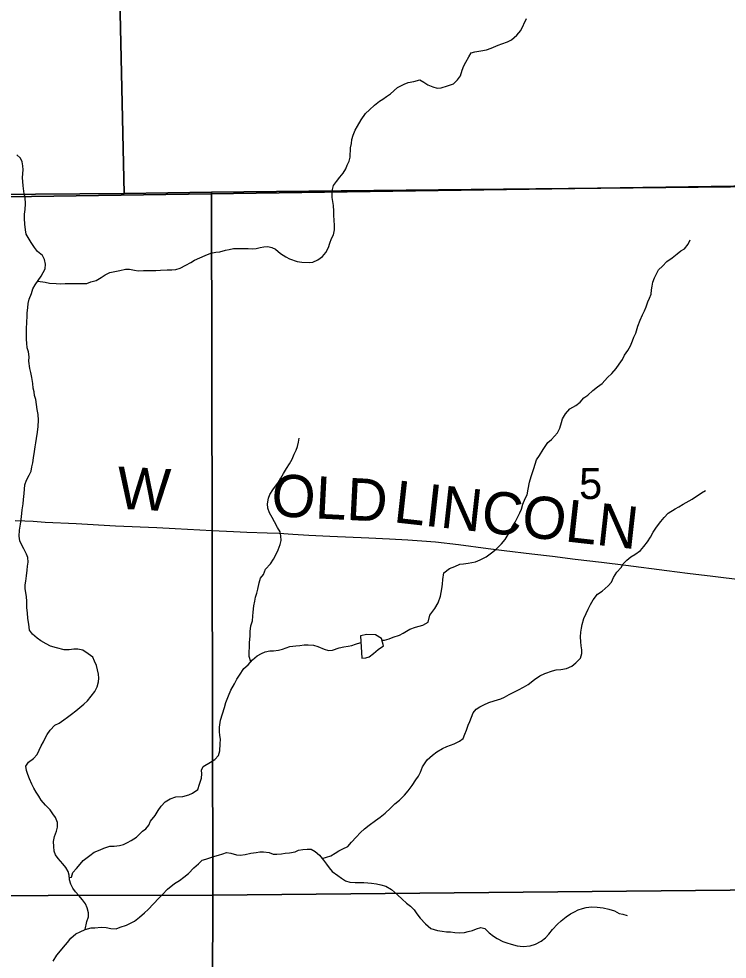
# Model space of a CAD drawing. Extents: x 1985906 to 2360102, y 891258 to 1222054.
# Drawn here: x 2080365 to 2085399, y 1019793 to 1026480 of the extents above; entities that cross this region are included whole.
import ezdxf

# ---------------------------------------------------------------- set-up
doc = ezdxf.new("R2010")
doc.units = 0
for name, color, linetype in [('GM_X_County_Road', 7, 'Continuous'), ('GM_X_County_Road_Text', 7, 'Continuous'), ('GM_X_Minor_Lake', 7, 'Continuous'), ('GM_X_Minor_River', 7, 'Continuous'), ('GM_X_Section', 7, 'Continuous'), ('GM_X_Section_Text', 7, 'Continuous'), ('GM_X_Township', 7, 'Continuous')]:
    doc.layers.add(name, color=color, linetype=linetype)

msp = doc.modelspace()

# ---------------------------------------------------------------- linework, layer by layer
at = {"layer": 'GM_X_County_Road'}
msp.add_lwpolyline([(2080338.1, 1022911.8), (2080407.5, 1022910), (2080466.6, 1022907.4), (2080551.7, 1022901.3), (2080773.4, 1022890.3), (2081051.5, 1022875.3), (2081346.3, 1022861.6), (2081477, 1022855.9), (2081738.7, 1022842.4), (2081889.7, 1022835.1), (2081985.2, 1022829.9), (2082129.4, 1022824.7), (2082215.4, 1022821.2), (2082311.9, 1022814.6), (2082426.6, 1022808.9), (2082574.1, 1022801.9), (2082852.1, 1022788.3), (2082999.5, 1022781.1), (2083130.5, 1022774.8), (2083228.7, 1022768.7), (2083326.6, 1022760.2), (2083489.5, 1022741.9), (2083701, 1022714.4), (2083815, 1022700.1), (2084010.3, 1022675.8), (2084156.8, 1022657.8), (2084319.6, 1022637.4), (2084505.1, 1022615.9), (2084678.7, 1022595), (2084970.8, 1022556.5), (2085117.1, 1022537.5), (2085296.1, 1022515.5), (2085507.3, 1022489.8)], dxfattribs=at)
at = {"layer": 'GM_X_Minor_Lake'}
for points in [[(2082802, 1021932.9), (2082830, 1021935.1), (2082855.9, 1021943.3), (2082885.8, 1021965.5), (2082919.6, 1021995.7), (2082957.5, 1022022), (2082943.2, 1022073.9), (2082899, 1022099.7), (2082839, 1022101.4), (2082793.1, 1022091.1)], [(2082793.1, 1022091.1), (2082802, 1021932.9)]]:
    msp.add_lwpolyline(points, dxfattribs=at)
at = {"layer": 'GM_X_Minor_River'}
for points in [[(2083307.3, 1025995.4), (2083337.4, 1025987.5), (2083365.4, 1025989.6), (2083411.4, 1026003.9), (2083453.4, 1026018.1), (2083483.4, 1026046.4), (2083503.2, 1026074.6), (2083515.1, 1026114.8), (2083526.9, 1026144.9), (2083540.8, 1026171.1), (2083562.7, 1026209.3), (2083580.5, 1026237.5), (2083606.5, 1026245.7), (2083648.6, 1026251.9), (2083688.6, 1026260.1), (2083722.6, 1026272.3), (2083770.6, 1026292.6), (2083798.6, 1026302.8), (2083838.6, 1026317), (2083866.6, 1026331.2), (2083904.5, 1026363.5), (2083932.4, 1026397.7), (2083974, 1026482.2)], [(2080499.5, 1024614.7), (2080553.2, 1024607.7), (2080583.3, 1024599.8), (2080629.4, 1024598), (2080661.4, 1024596.2), (2080693.5, 1024598.3), (2080791.7, 1024598.8), (2080817.7, 1024596.9), (2080847.8, 1024599), (2080875.8, 1024609.2), (2080913.8, 1024619.4), (2080949.8, 1024641.7), (2080977.7, 1024659.9), (2081011.7, 1024676.1), (2081047.7, 1024682.3), (2081083.8, 1024690.5), (2081123.8, 1024700.7), (2081151.8, 1024700.8), (2081187.9, 1024692.9), (2081214, 1024689), (2081252.1, 1024689.2), (2081278.1, 1024691.3), (2081312.2, 1024689.5), (2081338.3, 1024689.6), (2081372.3, 1024691.8), (2081418.4, 1024694), (2081452.4, 1024696.2), (2081480.5, 1024698.3), (2081512.5, 1024706.5), (2081552.5, 1024728.7), (2081588.4, 1024747), (2081614.4, 1024763.2), (2081650.4, 1024781.4), (2081688.4, 1024797.6), (2081728.4, 1024813.8), (2081764.4, 1024820), (2081794.4, 1024824.2), (2081834.5, 1024834.4), (2081860.5, 1024840.6), (2081890.5, 1024846.7), (2081994.7, 1024847.2), (2082026.8, 1024845.3), (2082052.8, 1024847.5), (2082080.8, 1024853.6), (2082106.9, 1024859.8), (2082134.9, 1024859.9), (2082163, 1024854), (2082189.1, 1024842.1), (2082225.3, 1024812.1), (2082261.5, 1024788.2), (2082287.7, 1024774.3), (2082343.9, 1024754.4), (2082376, 1024748.6), (2082428.1, 1024746.8), (2082454.1, 1024748.9), (2082490.1, 1024767.2), (2082522, 1024789.4), (2082547.9, 1024817.6), (2082565.8, 1024853.8), (2082575.6, 1024884), (2082587.5, 1024918.2), (2082601.4, 1024944.3), (2082609.2, 1024978.5), (2082609, 1025008.6), (2082606.8, 1025050.7), (2082604.7, 1025078.8), (2082604.5, 1025112.9), (2082600.3, 1025153.1), (2082592, 1025209.2), (2082591.8, 1025235.3), (2082593.7, 1025267.4), (2082601.5, 1025295.6), (2082623.4, 1025323.8), (2082645.3, 1025354), (2082669.2, 1025382.2), (2082689.1, 1025412.4), (2082699, 1025438.6), (2082712.9, 1025468.7), (2082718.7, 1025496.9), (2082722.4, 1025563.1), (2082728.2, 1025593.3), (2082732.1, 1025621.4), (2082742, 1025653.5), (2082755.8, 1025687.7), (2082771.7, 1025715.9), (2082797.5, 1025762.2), (2082829.3, 1025806.5), (2082857.2, 1025832.7), (2082893.2, 1025865), (2082927.1, 1025895.3), (2082953, 1025909.4), (2082979, 1025927.6), (2083007, 1025945.8), (2083056.8, 1025992.2), (2083102.8, 1026016.5), (2083132.8, 1026026.7), (2083172.8, 1026034.9), (2083214.8, 1026045.1), (2083243, 1026029.2), (2083271.1, 1026011.3), (2083307.3, 1025995.4)], [(2080383.5, 1022938.9), (2080389.3, 1022987.1), (2080395.1, 1023031.3), (2080398.9, 1023061.4), (2080402.7, 1023103.6), (2080404.5, 1023135.7), (2080408.4, 1023165.8), (2080420.2, 1023200), (2080438.1, 1023234.2), (2080451.9, 1023264.4), (2080457.8, 1023294.5), (2080463.7, 1023322.7), (2080469.5, 1023358.8), (2080475.3, 1023403), (2080481.1, 1023435.2), (2080485, 1023465.3), (2080490.8, 1023495.4), (2080496.6, 1023539.6), (2080502.4, 1023579.8), (2080504.2, 1023626), (2080502, 1023666.1), (2080495.8, 1023702.2), (2080485.4, 1023772.4), (2080477.2, 1023802.5), (2080473.1, 1023828.5), (2080466.9, 1023854.6), (2080464.7, 1023886.7), (2080456.5, 1023928.8), (2080450.3, 1023964.9), (2080444.1, 1023993), (2080435.9, 1024045.2), (2080437.7, 1024077.3), (2080433.5, 1024111.4), (2080425.4, 1024139.4), (2080421.2, 1024173.6), (2080419, 1024199.6), (2080418.6, 1024271.9), (2080422.4, 1024328.1), (2080424.2, 1024360.2), (2080424, 1024390.4), (2080427.9, 1024424.5), (2080431.7, 1024454.6), (2080439.6, 1024486.8), (2080455.4, 1024527), (2080465.2, 1024559.2), (2080481.1, 1024589.3), (2080503, 1024619.5), (2080524.9, 1024649.8), (2080552.7, 1024702.1), (2080554.5, 1024736.2), (2080546.3, 1024768.3), (2080534.2, 1024796.3), (2080497.9, 1024826.3), (2080475.7, 1024854.3), (2080453.5, 1024888.3), (2080437.4, 1024914.3), (2080417.1, 1024948.3), (2080413, 1024980.4), (2080408.7, 1025020.6), (2080406.5, 1025060.7), (2080406.4, 1025090.8), (2080410.2, 1025124.9), (2080412, 1025165.1), (2080409.8, 1025209.2), (2080403.6, 1025235.3), (2080395.3, 1025291.5), (2080391, 1025351.7), (2080394.7, 1025405.9), (2080392.6, 1025434), (2080388.4, 1025464.1), (2080376.2, 1025490.1), (2080350.1, 1025512.1)], [(2083425.3, 1022571.4), (2083463.3, 1022585.7), (2083499.3, 1022601.9), (2083525.3, 1022604), (2083559.4, 1022608.2), (2083609.4, 1022618.4), (2083643.4, 1022632.7), (2083685.4, 1022654.9), (2083725.3, 1022683.2), (2083757.2, 1022709.4), (2083795.1, 1022745.8), (2083821, 1022778), (2083850.8, 1022824.3), (2083868.7, 1022862.5), (2083892.5, 1022900.8), (2083926.2, 1022967.2), (2083938.1, 1022993.3), (2083947.9, 1023029.5), (2083963.8, 1023067.7), (2083977.7, 1023093.8), (2083985.5, 1023136), (2083995.2, 1023184.3), (2084007, 1023224.5), (2084024.8, 1023282.8), (2084044.5, 1023343.1), (2084064.4, 1023375.3), (2084090.2, 1023417.5), (2084124, 1023467.9), (2084149.9, 1023488.1), (2084193.8, 1023536.5), (2084209.6, 1023568.6), (2084221.5, 1023608.8), (2084229.3, 1023635), (2084249.2, 1023671.2), (2084281.1, 1023705.5), (2084323, 1023729.7), (2084355, 1023754), (2084380.9, 1023784.2), (2084408.8, 1023804.4), (2084444.7, 1023836.7), (2084478.6, 1023862.9), (2084510.6, 1023887.2), (2084548.4, 1023929.5), (2084578.3, 1023957.7), (2084610.2, 1023994), (2084632.1, 1024024.2), (2084654, 1024058.4), (2084669.8, 1024088.6), (2084693.7, 1024120.9), (2084711.6, 1024155.1), (2084725.4, 1024189.3), (2084735.3, 1024215.4), (2084749.2, 1024245.6), (2084762.9, 1024293.8), (2084780.8, 1024338), (2084796.6, 1024374.2), (2084810.5, 1024404.4), (2084824.3, 1024432.6), (2084834.2, 1024466.8), (2084848.1, 1024492.9), (2084858, 1024521.1), (2084861.8, 1024553.2), (2084865.7, 1024579.3), (2084871.5, 1024607.4), (2084883.4, 1024637.6), (2084911.2, 1024693.9), (2084939.1, 1024720.2), (2084971, 1024754.4), (2085008.9, 1024780.7), (2085042.8, 1024809), (2085068.8, 1024829.2), (2085094.7, 1024845.3), (2085120.6, 1024877.6), (2085136.5, 1024907.8)], [(2082014.3, 1021908.1), (2082001.8, 1021944.7), (2082001.6, 1021980.8), (2082003.5, 1022008.9), (2082003.3, 1022043), (2082009, 1022093.3), (2082008.9, 1022123.4), (2082014.7, 1022163.5), (2082024.5, 1022199.7), (2082028.4, 1022231.8), (2082030.2, 1022260), (2082036, 1022306.2), (2082041.8, 1022338.3), (2082047.7, 1022366.4), (2082055.6, 1022394.6), (2082063.4, 1022424.7), (2082073.2, 1022468.9), (2082083.1, 1022503.1), (2082105, 1022529.3), (2082118.8, 1022565.5), (2082152.7, 1022603.8), (2082174.5, 1022638), (2082194.4, 1022672.2), (2082208.3, 1022704.4), (2082222.1, 1022742.6), (2082229.9, 1022770.7), (2082227.8, 1022802.8), (2082221.6, 1022832.9), (2082203.4, 1022862.9), (2082181.2, 1022903), (2082165, 1022933), (2082146.8, 1022967), (2082134.6, 1022999.1), (2082132.4, 1023031.2), (2082138.2, 1023071.4), (2082148.1, 1023097.5), (2082170, 1023129.8), (2082189.9, 1023155.9), (2082209.8, 1023184.1), (2082227.6, 1023212.3), (2082245.5, 1023246.5), (2082267.4, 1023282.8), (2082289.2, 1023315), (2082307.1, 1023349.2), (2082320.9, 1023383.4), (2082334.8, 1023411.5), (2082344.7, 1023437.7), (2082352.6, 1023469.8), (2082358.4, 1023497.9)], [(2082521.3, 1020508.7), (2082582.3, 1020528.1), (2082614.3, 1020546.3), (2082640.2, 1020562.5), (2082668.2, 1020576.7), (2082702.2, 1020592.9), (2082728.1, 1020625.2), (2082762, 1020659.4), (2082793.9, 1020693.7), (2082821.8, 1020719.9), (2082855.7, 1020746.2), (2082899.6, 1020778.5), (2082933.6, 1020802.7), (2082969.5, 1020831), (2083005.4, 1020867.3), (2083037.3, 1020897.6), (2083069.2, 1020923.8), (2083105.1, 1020958.1), (2083131, 1020990.3), (2083160.8, 1021028.6), (2083186.7, 1021068.9), (2083204.6, 1021095), (2083220.4, 1021123.2), (2083234.3, 1021161.4), (2083268.1, 1021209.8), (2083304, 1021244), (2083335.9, 1021268.3), (2083375.9, 1021290.5), (2083405.9, 1021304.7), (2083431.9, 1021314.9), (2083459.9, 1021325), (2083497.8, 1021343.3), (2083523.8, 1021361.5), (2083535.7, 1021393.6), (2083545.5, 1021421.8), (2083557.4, 1021456), (2083569.2, 1021484.1), (2083581.1, 1021514.3), (2083595, 1021544.5), (2083614.9, 1021570.6), (2083640.8, 1021586.8), (2083670.8, 1021601), (2083704.8, 1021617.2), (2083742.8, 1021629.4), (2083790.8, 1021643.7), (2083816.8, 1021655.9), (2083850.8, 1021674.1), (2083882.8, 1021692.3), (2083916.8, 1021708.5), (2083952.7, 1021726.8), (2083984.7, 1021747), (2084028.6, 1021781.3), (2084066.5, 1021807.6), (2084102.5, 1021823.8), (2084156.5, 1021844.1), (2084184.5, 1021850.2), (2084216.6, 1021852.4), (2084256.6, 1021860.6), (2084294.6, 1021876.8), (2084324.5, 1021901.1), (2084356.4, 1021933.3), (2084366.3, 1021965.5), (2084366.1, 1021993.6), (2084362, 1022021.7), (2084359.8, 1022049.8), (2084355.7, 1022083.9), (2084359.5, 1022118), (2084363.3, 1022146.2), (2084369.2, 1022172.3), (2084381, 1022214.5), (2084396.9, 1022250.7), (2084410.7, 1022282.9), (2084426.6, 1022315.1), (2084446.4, 1022349.3), (2084476.3, 1022387.5), (2084510.3, 1022409.8), (2084554.1, 1022448.1), (2084576, 1022474.3), (2084591.9, 1022506.5), (2084613.8, 1022544.7), (2084645.6, 1022577), (2084659.5, 1022603.2), (2084685.5, 1022629.4), (2084715.4, 1022653.6), (2084743.3, 1022669.8), (2084783.3, 1022700.1), (2084807.2, 1022728.3), (2084833.1, 1022760.5), (2084854.9, 1022792.8), (2084872.8, 1022828.9), (2084896.6, 1022865.2), (2084928.5, 1022905.5), (2084952.4, 1022933.7), (2084980.3, 1022963.9), (2085030.2, 1022994.3), (2085056.2, 1023010.5), (2085086.2, 1023028.7), (2085150.1, 1023065.1), (2085216, 1023109.5), (2085244, 1023125.7)], [(2080835.7, 1020004.3), (2080849.4, 1020060.5), (2080859.2, 1020094.7), (2080861.1, 1020122.8), (2080850.9, 1020156.9), (2080838.7, 1020187), (2080816.5, 1020215), (2080790.3, 1020244.9), (2080768.1, 1020270.9), (2080750, 1020297), (2080735.8, 1020325), (2080725.6, 1020357.1), (2080723.4, 1020389.2), (2080715.3, 1020415.2), (2080699.1, 1020445.3), (2080678.9, 1020471.3), (2080644.7, 1020509.3), (2080626.5, 1020535.3), (2080616.3, 1020561.3), (2080614.2, 1020593.4), (2080612, 1020629.5), (2080617.8, 1020665.7), (2080631.6, 1020701.9), (2080639.5, 1020732), (2080639.3, 1020764.2), (2080625.1, 1020800.2), (2080606.9, 1020826.2), (2080586.7, 1020854.2), (2080554.5, 1020888.2), (2080524.3, 1020924.2), (2080506.1, 1020952.2), (2080487.9, 1020980.3), (2080471.7, 1021008.3), (2080457.5, 1021038.3), (2080441.3, 1021074.4), (2080429.1, 1021106.5), (2080419, 1021134.5), (2080414.8, 1021164.6), (2080434.7, 1021192.8), (2080468.6, 1021219), (2080496.5, 1021249.3), (2080524.3, 1021309.6), (2080540.1, 1021337.8), (2080552, 1021364), (2080565.9, 1021390.1), (2080587.8, 1021420.3), (2080621.7, 1021456.6), (2080651.7, 1021470.8), (2080685.6, 1021495), (2080711.6, 1021513.2), (2080739.5, 1021535.4), (2080769.4, 1021557.7), (2080799.4, 1021581.9), (2080827.3, 1021606.1), (2080853.2, 1021630.3), (2080879.1, 1021662.5), (2080905, 1021696.8), (2080920.8, 1021729), (2080930.7, 1021765.2), (2080934.5, 1021791.3), (2080930.4, 1021819.3), (2080924.2, 1021851.4), (2080916, 1021881.5), (2080903.9, 1021911.6), (2080891.7, 1021939.6), (2080857.5, 1021963.5), (2080819.3, 1021989.5), (2080783.2, 1021997.3), (2080757.1, 1021997.2), (2080723.1, 1021993), (2080687, 1021992.9), (2080632.8, 1022006.7), (2080590.7, 1022018.5), (2080558.6, 1022034.4), (2080520.4, 1022056.3), (2080494.2, 1022076.3), (2080462, 1022104.2), (2080441.8, 1022132.3), (2080435.6, 1022174.4), (2080429.4, 1022214.5), (2080427.2, 1022254.6), (2080423, 1022290.8), (2080422.7, 1022336.9), (2080420.5, 1022371), (2080414.4, 1022399.1), (2080410.2, 1022429.2), (2080410.1, 1022455.3), (2080413.9, 1022481.4), (2080419.8, 1022519.6), (2080423.6, 1022559.7), (2080427.4, 1022587.8), (2080431.3, 1022616), (2080429.1, 1022648.1), (2080419, 1022674.1), (2080400.7, 1022710.2), (2080386.6, 1022736.2), (2080372.4, 1022768.2), (2080368.2, 1022800.3), (2080370, 1022844.5), (2080375.8, 1022886.7), (2080383.5, 1022938.9)], [(2082946.4, 1022062.3), (2082963.1, 1022061.5), (2082997.1, 1022071.7), (2083025.1, 1022081.8), (2083071.1, 1022096.1), (2083097.1, 1022110.3), (2083143, 1022140.6), (2083185, 1022154.8), (2083237, 1022169.1), (2083273, 1022189.4), (2083286.8, 1022239.6), (2083320.6, 1022285.9), (2083344.4, 1022326.2), (2083362.2, 1022374.4), (2083372, 1022426.7), (2083375.8, 1022458.8), (2083377.6, 1022492.9), (2083385.4, 1022539.1), (2083425.3, 1022571.4)], [(2080724.4, 1020374.2), (2080739.5, 1020375.2), (2080749.4, 1020409.4), (2080775.3, 1020437.6), (2080801.2, 1020467.8), (2080821.1, 1020494), (2080869, 1020530.3), (2080900.9, 1020552.6), (2080942.9, 1020570.8), (2080968.9, 1020583), (2081010.9, 1020595.2), (2081043, 1020595.4), (2081081, 1020601.6), (2081109, 1020607.7), (2081137, 1020621.9), (2081163, 1020636.1), (2081200.9, 1020660.3), (2081242.8, 1020702.7), (2081268.8, 1020718.9), (2081288.7, 1020745), (2081300.6, 1020773.2), (2081334.4, 1020815.5), (2081356.3, 1020849.7), (2081376.1, 1020881.9), (2081404, 1020912.2), (2081440, 1020932.4), (2081480, 1020946.7), (2081530.1, 1020948.9), (2081574.1, 1020961.1), (2081600.1, 1020973.3), (2081636, 1020999.6), (2081649.8, 1021037.8), (2081663.7, 1021080), (2081665.5, 1021110.1), (2081663.4, 1021136.2), (2081675.3, 1021162.3), (2081727.2, 1021194.7), (2081759.1, 1021212.9), (2081783, 1021241.1), (2081792.9, 1021275.3), (2081796.6, 1021323.5), (2081798.5, 1021357.6), (2081794.3, 1021383.7), (2081792.2, 1021411.8), (2081792, 1021441.9), (2081797.8, 1021492.1), (2081827.4, 1021582.6), (2081837.2, 1021618.7), (2081855, 1021665), (2081872.8, 1021705.2), (2081896.6, 1021751.5), (2081914.5, 1021783.7), (2081932.4, 1021811.9), (2081964.2, 1021860.2), (2081994.1, 1021886.4), (2082026, 1021920.7), (2082059.9, 1021949), (2082089.9, 1021967.2), (2082115.9, 1021977.3), (2082149.9, 1021985.5), (2082175.9, 1021985.6), (2082210, 1021989.8), (2082240, 1021998), (2082292, 1022016.3), (2082334.1, 1022020.5), (2082362.1, 1022024.6), (2082392.1, 1022028.8), (2082422.2, 1022028.9), (2082458.3, 1022025), (2082490.4, 1022015.2), (2082534.6, 1021997.3), (2082564.7, 1021987.4), (2082594.7, 1021989.5), (2082640.7, 1022005.8), (2082674.7, 1022014), (2082704.8, 1022018.1), (2082730.8, 1022024.3), (2082758.8, 1022032.4), (2082795.7, 1022044.9)], [(2080608.4, 1019778.4), (2080636.2, 1019820.7), (2080660.1, 1019850.9), (2080682, 1019877.1), (2080709.9, 1019911.4), (2080735.8, 1019941.6), (2080769.7, 1019971.8), (2080801.7, 1019988.1), (2080835.7, 1020004.3), (2080879.7, 1020014.5), (2080905.7, 1020016.6), (2080949.8, 1020020.8), (2080985.9, 1020017), (2081020, 1020011.1), (2081056.1, 1020009.3), (2081086.1, 1020019.5), (2081130.1, 1020033.7), (2081186, 1020064.1), (2081222, 1020090.3), (2081257.9, 1020122.6), (2081283.8, 1020144.8), (2081359.5, 1020225.5), (2081385.4, 1020253.7), (2081421.3, 1020290), (2081471.2, 1020330.4), (2081507.1, 1020352.6), (2081537.1, 1020376.8), (2081571, 1020403.1), (2081608.9, 1020441.4), (2081642.8, 1020469.7), (2081668.7, 1020495.9), (2081694.7, 1020504), (2081758.7, 1020524.4), (2081784.7, 1020532.5), (2081814.7, 1020542.7), (2081840.8, 1020550.8), (2081872.8, 1020547), (2081911, 1020535.1), (2081937, 1020533.2), (2081973.1, 1020537.4), (2082013.1, 1020547.6), (2082051.2, 1020551.8), (2082077.2, 1020555.9), (2082103.2, 1020556.1), (2082143.3, 1020550.2), (2082173.5, 1020540.3), (2082199.5, 1020540.4), (2082231.6, 1020542.6), (2082257.6, 1020546.7), (2082289.6, 1020548.9), (2082327.7, 1020557.1), (2082353.7, 1020567.2), (2082383.7, 1020573.4), (2082413.7, 1020575.5), (2082441.8, 1020575.7), (2082471.9, 1020557.7), (2082502.1, 1020531.8), (2082530.4, 1020497.8), (2082550.6, 1020467.8), (2082570.7, 1020441.8)], [(2082570.7, 1020441.8), (2082592.9, 1020415.8), (2082633.1, 1020387.8), (2082659.3, 1020369.9), (2082687.4, 1020350), (2082717.5, 1020340.1), (2082755.6, 1020338.2), (2082815.8, 1020338.5), (2082845.8, 1020334.6), (2082871.9, 1020332.7), (2082906, 1020328.9), (2082938.1, 1020321), (2082974.2, 1020311.1), (2083012.4, 1020287.2), (2083056.7, 1020251.3), (2083088.9, 1020219.3), (2083121.1, 1020191.3), (2083149.3, 1020169.4), (2083173.5, 1020143.4), (2083193.6, 1020115.4), (2083217.9, 1020083.4), (2083256.1, 1020043.4), (2083292.4, 1020011.5), (2083340.5, 1019997.6), (2083372.6, 1019991.8), (2083404.7, 1019987.9), (2083432.8, 1019986), (2083462.9, 1019982.1), (2083498.9, 1019980.3), (2083533, 1019982.4), (2083559, 1019988.6), (2083589, 1019996.8), (2083617, 1020008.9), (2083649, 1020019.1), (2083677.1, 1020011.2), (2083707.3, 1019981.2), (2083737.5, 1019957.3), (2083763.7, 1019939.3), (2083803.9, 1019917.4), (2083834, 1019909.5), (2083864.1, 1019899.6), (2083906.2, 1019887.8), (2083950.3, 1019884), (2083998.4, 1019888.2), (2084036.4, 1019898.4), (2084076.4, 1019920.7), (2084108.3, 1019944.9), (2084132.2, 1019971.1), (2084158.1, 1020003.4), (2084192, 1020041.7), (2084219.9, 1020065.9), (2084255.8, 1020094.1), (2084285.8, 1020114.3), (2084313.7, 1020130.5), (2084339.7, 1020144.7), (2084369.7, 1020152.9), (2084397.7, 1020161), (2084435.8, 1020165.2), (2084473.9, 1020163.4), (2084518, 1020157.5), (2084558.1, 1020147.7), (2084598.3, 1020135.8), (2084632.4, 1020117.9), (2084658.5, 1020112), (2084688.6, 1020102.1)]]:
    msp.add_lwpolyline(points, dxfattribs=at)
at = {"layer": 'GM_X_Section'}
for points in [[(2080995.7, 1030588.7), (2081113.9, 1025238.2), (2077007.6, 1025208.2), (2076964, 1030463), (2076961.6, 1030541)], [(2086502.7, 1030641.5), (2086576.7, 1025296.9), (2081734.2, 1025247.3), (2081113.9, 1025238.2), (2080995.7, 1030588.7)], [(2086576.7, 1025296.9), (2087101, 1025303.4), (2087135.3, 1020300.8), (2081744.5, 1020248.5), (2081734.2, 1025247.3)], [(2081113.9, 1025238.2), (2081734.2, 1025247.3), (2081744.5, 1020248.5), (2077063.9, 1020237.7), (2077007.6, 1025208.2)], [(2087135.3, 1020300.8), (2087111.5, 1014901.6), (2081724.6, 1014883.5), (2081744.5, 1020248.5)], [(2081744.5, 1020248.5), (2081724.6, 1014883.5), (2077100, 1014883), (2077065.6, 1019893.6), (2077063.9, 1020237.7)]]:
    msp.add_lwpolyline(points, close=True, dxfattribs=at)
at = {"layer": 'GM_X_Township'}
for points in [[(2095094.6, 1025388.3), (2092097.4, 1025367.8), (2089225.7, 1025330.9), (2087095.5, 1025303.4), (2086577.8, 1025306.1), (2081728.4, 1025236.6), (2079654.5, 1025204.9), (2076405.9, 1025155.2), (2074264, 1025122.4), (2071602.1, 1025081.7), (2071939.9, 1030867.8), (2072018.3, 1033424.1), (2072055.1, 1036106.6), (2072120.2, 1038512.6), (2072112.2, 1041354.4), (2072178.7, 1046252), (2072142.8, 1047459), (2072218.3, 1051577.8), (2072166.7, 1051922.6), (2071926.7, 1054555.3)], [(2071887.5, 1008769), (2071861.2, 1011952), (2071852.3, 1012905.1), (2071829.8, 1014456.9), (2071696.9, 1021700.4), (2071562, 1025081.6), (2071602.1, 1025081.7), (2074264, 1025122.4), (2076405.9, 1025155.2), (2079654.5, 1025204.9), (2081728.4, 1025236.6), (2086577.8, 1025306.1), (2087095.5, 1025303.4), (2089225.7, 1025330.9), (2092097.4, 1025367.8), (2095094.6, 1025388.3)]]:
    msp.add_lwpolyline(points, dxfattribs=at)

# ---------------------------------------------------------------- texts
at = {"layer": 'GM_X_County_Road_Text'}
for s, rotation, p in [('W', 357.10158, (2081057, 1022997.1)), ('OLD', 357.07201, (2082154.7, 1022944.3)), ('LINCOLN', 353.63376, (2083021.3, 1022900.7))]:
    msp.add_text(s, height=300, rotation=rotation, dxfattribs=at).set_placement(p)
at = {"layer": 'GM_X_Section_Text'}
msp.add_text('5', height=221, rotation=0.00001, dxfattribs=at).set_placement((2084346.6, 1023065))

doc.saveas('drawing.dxf')
